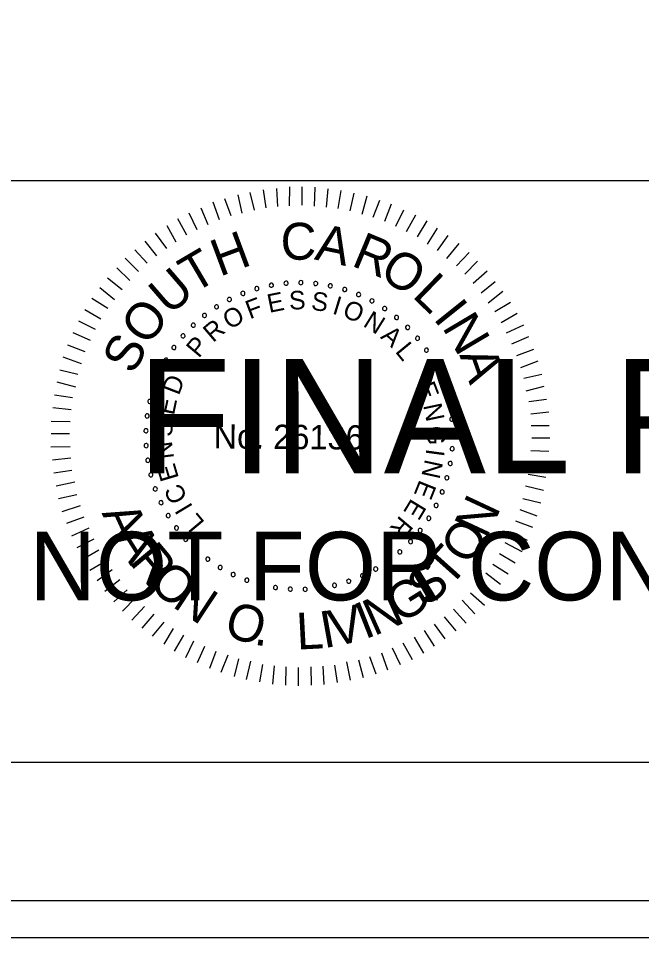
# Model space of a CAD drawing. Extents: x 967 to 1326, y 964 to 3144.
# Drawn here: x 1170.56 to 1189.3, y 1243.72 to 1271.36 of the extents above; entities that cross this region are included whole.
import ezdxf

# ---------------------------------------------------------------- set-up
doc = ezdxf.new("R2010")
doc.units = 0
for name, color, linetype in [('RD_XS_EwShp', 7, 'Continuous'), ('RD_XS_ExPaveRet', 7, 'Continuous'), ('RD_XS_TX_Elev_EX', 7, 'Continuous'), ('RD_XS_TX_Elev_PR', 7, 'Continuous'), ('RD_XS_TX_Station', 7, 'Continuous')]:
    doc.layers.add(name, color=color, linetype=linetype)

msp = doc.modelspace()

# ---------------------------------------------------------------- linework, layer by layer
at = {"layer": 'RD_XS_ExPaveRet'}
for points in [[(967.409, 1243.72), (1326.285, 1243.72), (1326.285, 1463.72), (967.409, 1463.72)], [(988.525, 1244.84), (1326.285, 1244.84), (1326.285, 1462.6), (988.525, 1462.6)]]:
    msp.add_lwpolyline(points, close=True, dxfattribs=at)
at = {"layer": 'RD_XS_TX_Elev_EX'}
for p, q in [((996.114, 1266.486), (1323.886, 1266.486)), ((1323.886, 1248.983), (996.114, 1248.983))]:
    msp.add_line(p, q, dxfattribs=at)
at = {"layer": 'RD_XS_TX_Elev_PR'}
for p, q in [((1178.01, 1265.663), (1177.93, 1266.209)), ((1178.364, 1265.699), (1178.33, 1266.244)), ((1178.717, 1265.719), (1178.722, 1266.295)), ((1179.093, 1265.739), (1179.098, 1266.292)), ((1179.469, 1265.713), (1179.489, 1266.288)), ((1179.829, 1265.687), (1179.872, 1266.231)), ((1180.174, 1265.646), (1180.271, 1266.19)), ((1176.964, 1265.419), (1176.769, 1265.935)), ((1177.287, 1265.508), (1177.169, 1266.054)), ((1177.657, 1265.597), (1177.53, 1266.128)), ((1180.535, 1265.573), (1180.662, 1266.102)), ((1180.902, 1265.478), (1181.045, 1266.022)), ((1176.264, 1265.156), (1176.053, 1265.657)), ((1176.61, 1265.306), (1176.423, 1265.83)), ((1181.231, 1265.384), (1181.428, 1265.896)), ((1181.584, 1265.265), (1181.78, 1265.786)), ((1175.933, 1265.005), (1175.699, 1265.506)), ((1181.905, 1265.109), (1182.154, 1265.606)), ((1182.226, 1264.953), (1182.506, 1265.45)), ((1175.308, 1264.634), (1175.036, 1265.12)), ((1175.624, 1264.846), (1175.352, 1265.332)), ((1182.562, 1264.789), (1182.85, 1265.27)), ((1175.03, 1264.445), (1174.681, 1264.9)), ((1182.86, 1264.572), (1183.163, 1265.053)), ((1183.158, 1264.378), (1183.484, 1264.828)), ((1174.729, 1264.217), (1174.372, 1264.665)), ((1183.447, 1264.145), (1183.811, 1264.587)), ((1174.435, 1263.997), (1174.062, 1264.399)), ((1183.729, 1263.92), (1184.116, 1264.316)), ((1174.172, 1263.753), (1173.776, 1264.148)), ((1183.98, 1263.672), (1184.368, 1264.061)), ((1173.909, 1263.479), (1173.52, 1263.858)), ((1184.232, 1263.394), (1184.657, 1263.767)), ((1173.684, 1263.197), (1173.242, 1263.546)), ((1184.475, 1263.108), (1184.892, 1263.45)), ((1173.451, 1262.9), (1173.009, 1263.256)), ((1184.687, 1262.807), (1185.128, 1263.156)), ((1173.257, 1262.64), (1172.776, 1262.936)), ((1173.039, 1262.312), (1172.559, 1262.6)), ((1184.885, 1262.544), (1185.355, 1262.832)), ((1185.081, 1262.213), (1185.56, 1262.493)), ((1172.883, 1262.006), (1172.379, 1262.256)), ((1185.24, 1261.904), (1185.756, 1262.145)), ((1172.727, 1261.677), (1172.215, 1261.904)), ((1185.399, 1261.573), (1185.907, 1261.791)), ((1172.571, 1261.333), (1172.051, 1261.53)), ((1185.549, 1261.226), (1186.057, 1261.414)), ((1172.461, 1260.974), (1171.91, 1261.178)), ((1185.669, 1260.865), (1186.185, 1261.06)), ((1172.351, 1260.652), (1171.807, 1260.787)), ((1185.759, 1260.541), (1186.297, 1260.667)), ((1172.286, 1260.276), (1171.727, 1260.419)), ((1185.832, 1260.165), (1186.371, 1260.298)), ((1172.191, 1259.955), (1171.647, 1260.029)), ((1185.906, 1259.842), (1186.436, 1259.906)), ((1172.15, 1259.587), (1171.598, 1259.653)), ((1185.964, 1259.473), (1186.51, 1259.53)), ((1172.124, 1259.234), (1171.548, 1259.239)), ((1185.977, 1259.12), (1186.514, 1259.115)), ((1172.105, 1258.866), (1171.545, 1258.871)), ((1185.997, 1258.751), (1186.542, 1258.747)), ((1172.118, 1258.482), (1171.542, 1258.471)), ((1185.971, 1258.368), (1186.508, 1258.348)), ((1172.138, 1258.136), (1171.585, 1258.072)), ((1185.952, 1258.022), (1186.497, 1257.949)), ((1172.173, 1257.768), (1171.627, 1257.688)), ((1185.888, 1257.655), (1186.417, 1257.566)), ((1172.262, 1257.414), (1171.701, 1257.296)), ((1185.808, 1257.302), (1186.345, 1257.175)), ((1172.321, 1257.037), (1171.774, 1256.911)), ((1185.729, 1256.926), (1186.265, 1256.792)), ((1172.425, 1256.707), (1171.871, 1256.519)), ((1185.634, 1256.597), (1186.146, 1256.401)), ((1172.53, 1256.36), (1172.007, 1256.173)), ((1185.508, 1256.253), (1186.013, 1256.057)), ((1172.681, 1256.029), (1172.165, 1255.788)), ((1172.831, 1255.705), (1172.323, 1255.441)), ((1185.352, 1255.924), (1185.857, 1255.675)), ((1185.188, 1255.603), (1185.7, 1255.33)), ((1172.982, 1255.374), (1172.497, 1255.094)), ((1185.024, 1255.274), (1185.498, 1254.987)), ((1173.194, 1255.042), (1172.709, 1254.762)), ((1184.822, 1254.946), (1185.288, 1254.658)), ((1173.384, 1254.78), (1172.936, 1254.453)), ((1184.62, 1254.687), (1185.055, 1254.353)), ((1173.612, 1254.478), (1173.164, 1254.129)), ((1184.403, 1254.389), (1184.814, 1254.033)), ((1173.832, 1254.177), (1173.437, 1253.812)), ((1184.155, 1254.092), (1184.574, 1253.72)), ((1174.091, 1253.945), (1173.689, 1253.541)), ((1183.899, 1253.864), (1184.28, 1253.454)), ((1174.35, 1253.674), (1173.97, 1253.263)), ((1183.644, 1253.597), (1184.024, 1253.18)), ((1174.64, 1253.442), (1174.275, 1253.022)), ((1174.937, 1253.209), (1174.58, 1252.782)), ((1183.358, 1253.37), (1183.715, 1252.944)), ((1175.212, 1253.014), (1174.932, 1252.549)), ((1182.764, 1252.952), (1183.059, 1252.482)), ((1183.065, 1253.141), (1183.384, 1252.709)), ((1175.525, 1252.812), (1175.245, 1252.331)), ((1182.463, 1252.755), (1182.743, 1252.269)), ((1175.83, 1252.633), (1175.588, 1252.136)), ((1176.159, 1252.477), (1175.94, 1251.98)), ((1181.8, 1252.431), (1182.041, 1251.93)), ((1182.124, 1252.581), (1182.396, 1252.08)), ((1176.503, 1252.321), (1176.307, 1251.816)), ((1176.855, 1252.211), (1176.651, 1251.69)), ((1177.177, 1252.1), (1177.05, 1251.572)), ((1181.122, 1252.175), (1181.31, 1251.652)), ((1181.476, 1252.28), (1181.664, 1251.771)), ((1177.545, 1252.036), (1177.409, 1251.484)), ((1177.897, 1251.933), (1177.808, 1251.412)), ((1178.25, 1251.892), (1178.207, 1251.34)), ((1178.603, 1251.866), (1178.598, 1251.313)), ((1178.978, 1251.84), (1178.974, 1251.295)), ((1179.355, 1251.86), (1179.365, 1251.307)), ((1179.715, 1251.88), (1179.749, 1251.327)), ((1180.061, 1251.915), (1180.149, 1251.393)), ((1180.423, 1252.012), (1180.541, 1251.458)), ((1180.791, 1252.07), (1180.926, 1251.54))]:
    msp.add_line(p, q, dxfattribs=at)
for centre, start, end in [((1178.609, 1263.397), 5.0653, 185.0653), ((1179.055, 1263.414), 359.5268, 179.5268), ((1179.055, 1263.414), 179.5268, 359.5268), ((1179.5, 1263.388), 353.9884, 173.9884), ((1177.312, 1263.091), 21.6807, 201.6807), ((1177.734, 1263.235), 16.1422, 196.1422), ((1177.734, 1263.235), 196.1422, 16.1422), ((1178.168, 1263.337), 10.6038, 190.6038), ((1178.168, 1263.337), 190.6038, 10.6038), ((1178.609, 1263.397), 185.0653, 5.0653), ((1179.5, 1263.388), 173.9884, 353.9884), ((1179.94, 1263.319), 168.4499, 348.4499), ((1179.94, 1263.319), 348.4499, 168.4499), ((1180.372, 1263.208), 162.9114, 342.9114), ((1180.372, 1263.208), 342.9114, 162.9114), ((1176.906, 1262.908), 27.2191, 207.2191), ((1176.906, 1262.908), 207.2191, 27.2191), ((1177.312, 1263.091), 201.6807, 21.6807), ((1180.79, 1263.056), 157.373, 337.373), ((1180.79, 1263.056), 337.373, 157.373), ((1181.193, 1262.864), 151.8345, 331.8345), ((1181.193, 1262.864), 331.8345, 151.8345), ((1176.52, 1262.686), 32.7576, 212.7576), ((1176.52, 1262.686), 212.7576, 32.7576), ((1181.574, 1262.634), 146.2961, 326.2961), ((1181.574, 1262.634), 326.2961, 146.2961), ((1176.156, 1262.428), 38.2961, 218.2961), ((1176.156, 1262.428), 218.2961, 38.2961), ((1181.932, 1262.368), 140.7576, 320.7576), ((1181.932, 1262.368), 320.7576, 140.7576), ((1175.82, 1262.135), 43.8345, 223.8345), ((1175.82, 1262.135), 223.8345, 43.8345), ((1182.263, 1262.069), 135.2191, 315.2191), ((1182.263, 1262.069), 315.2191, 135.2191), ((1175.513, 1261.812), 49.373, 229.373), ((1175.513, 1261.812), 229.373, 49.373), ((1182.563, 1261.74), 129.6807, 309.6807), ((1182.563, 1261.74), 309.6807, 129.6807), ((1175.239, 1261.461), 54.9114, 234.9114), ((1175.239, 1261.461), 234.9114, 54.9114), ((1182.83, 1261.383), 124.1422, 304.1422), ((1182.83, 1261.383), 304.1422, 124.1422), ((1175, 1261.085), 60.4499, 240.4499), ((1175, 1261.085), 240.4499, 60.4499), ((1183.061, 1261.002), 118.6038, 298.6038), ((1183.061, 1261.002), 298.6038, 118.6038), ((1174.798, 1260.687), 65.9884, 245.9884), ((1174.798, 1260.687), 245.9884, 65.9884), ((1183.255, 1260.601), 113.0653, 293.0653), ((1183.255, 1260.601), 293.0653, 113.0653), ((1174.636, 1260.272), 71.5268, 251.5268), ((1174.636, 1260.272), 251.5268, 71.5268), ((1183.408, 1260.182), 107.5268, 287.5268), ((1183.408, 1260.182), 287.5268, 107.5268), ((1174.514, 1259.843), 77.0653, 257.0653), ((1174.514, 1259.843), 257.0653, 77.0653), ((1183.521, 1259.751), 101.9884, 281.9884), ((1183.521, 1259.751), 281.9884, 101.9884), ((1174.435, 1259.405), 82.6038, 262.6038), ((1174.435, 1259.405), 262.6038, 82.6038), ((1183.592, 1259.311), 96.4499, 276.4499), ((1183.592, 1259.311), 276.4499, 96.4499), ((1174.398, 1258.961), 88.1422, 268.1422), ((1174.398, 1258.961), 268.1422, 88.1422), ((1183.619, 1258.866), 90.9114, 270.9114), ((1183.619, 1258.866), 270.9114, 90.9114), ((1174.404, 1258.515), 93.6807, 273.6807), ((1174.404, 1258.515), 273.6807, 93.6807), ((1183.604, 1258.421), 85.373, 265.373), ((1183.604, 1258.421), 265.373, 85.373), ((1174.453, 1258.072), 99.2191, 279.2191), ((1174.453, 1258.072), 279.2191, 99.2191), ((1183.546, 1257.979), 79.8345, 259.8345), ((1183.546, 1257.979), 259.8345, 79.8345), ((1174.545, 1257.636), 104.7576, 284.7576), ((1174.545, 1257.636), 284.7576, 104.7576), ((1183.445, 1257.545), 74.2961, 254.2961), ((1183.445, 1257.545), 254.2961, 74.2961), ((1174.678, 1257.211), 110.2961, 290.2961), ((1174.678, 1257.211), 290.2961, 110.2961), ((1183.303, 1257.122), 68.7576, 248.7576), ((1183.303, 1257.122), 248.7576, 68.7576), ((1174.852, 1256.8), 115.8345, 295.8345), ((1174.852, 1256.8), 295.8345, 115.8345), ((1183.121, 1256.716), 63.2191, 243.2191), ((1183.121, 1256.716), 243.2191, 63.2191), ((1175.065, 1256.409), 121.373, 301.373), ((1175.065, 1256.409), 301.373, 121.373), ((1182.9, 1256.328), 57.6807, 237.6807), ((1182.9, 1256.328), 237.6807, 57.6807), ((1175.314, 1256.039), 126.9114, 306.9114), ((1175.314, 1256.039), 306.9114, 126.9114), ((1182.643, 1255.964), 52.1422, 232.1422), ((1182.643, 1255.964), 232.1422, 52.1422), ((1175.598, 1255.696), 132.4499, 312.4499), ((1175.598, 1255.696), 312.4499, 132.4499), ((1182.353, 1255.627), 46.6038, 226.6038), ((1175.914, 1255.381), 137.9884, 317.9884), ((1175.914, 1255.381), 317.9884, 137.9884), ((1182.353, 1255.627), 226.6038, 46.6038), ((1176.258, 1255.099), 143.5268, 323.5268), ((1176.258, 1255.099), 323.5268, 143.5268), ((1182.03, 1255.319), 41.0653, 221.0653), ((1182.03, 1255.319), 221.0653, 41.0653), ((1176.629, 1254.851), 149.0653, 329.0653), ((1176.629, 1254.851), 329.0653, 149.0653), ((1181.305, 1254.803), 29.9884, 209.9884), ((1181.68, 1255.043), 35.5268, 215.5268), ((1181.68, 1255.043), 215.5268, 35.5268), ((1177.021, 1254.639), 154.6038, 334.6038), ((1177.021, 1254.639), 334.6038, 154.6038), ((1180.908, 1254.6), 24.4499, 204.4499), ((1180.908, 1254.6), 204.4499, 24.4499), ((1181.305, 1254.803), 209.9884, 29.9884), ((1177.432, 1254.467), 160.1422, 340.1422), ((1177.432, 1254.467), 340.1422, 160.1422), ((1177.858, 1254.335), 165.6807, 345.6807), ((1177.858, 1254.335), 345.6807, 165.6807), ((1178.294, 1254.245), 351.2191, 171.2191), ((1179.627, 1254.232), 7.8345, 187.8345), ((1180.065, 1254.313), 13.373, 193.373), ((1180.065, 1254.313), 193.373, 13.373), ((1180.494, 1254.436), 18.9114, 198.9114), ((1180.494, 1254.436), 198.9114, 18.9114), ((1178.294, 1254.245), 171.2191, 351.2191), ((1178.737, 1254.198), 356.7576, 176.7576), ((1178.737, 1254.198), 176.7576, 356.7576), ((1179.183, 1254.193), 2.2961, 182.2961), ((1179.183, 1254.193), 182.2961, 2.2961), ((1179.627, 1254.232), 187.8345, 7.8345)]:
    msp.add_arc(centre, 0.0627, start, end, dxfattribs=at)
at = {"layer": 'RD_XS_TX_Station'}
msp.add_lwpolyline([(967.409, 1243.72), (1326.285, 1243.72), (1326.285, 1463.72), (967.409, 1463.72)], close=True, dxfattribs=at)

# ---------------------------------------------------------------- texts
at = {"layer": 'RD_XS_EwShp'}
for s, height, p in [('FINAL PLANS', 3.4375, (1174.145, 1257.685)), ('NOT FOR CONSTRUCTION', 2.0625, (1170.901, 1253.86))]:
    msp.add_text(s, height=height, dxfattribs=at).set_placement(p)
at = {"layer": 'RD_XS_TX_Elev_PR'}
for s, height, rotation, p in [('C', 1.11, 359.5482, (1178.442, 1264.108)), ('A', 1.11, 348.1981, (1179.439, 1264.115)), ('H', 1.11, 20.3637, (1176.614, 1263.587)), ('R', 1.11, 337.4344, (1180.541, 1263.937)), ('T', 1.11, 30.4992, (1175.828, 1263.072)), ('O', 1.108, 326.5869, (1181.366, 1263.609)), ('U', 1.11, 40.8022, (1175.102, 1262.403)), ('L', 1.11, 315.9488, (1182.373, 1263.003)), ('E', 0.557, 11.4103, (1178.103, 1262.503)), ('S', 0.557, 2.208, (1178.709, 1262.601)), ('S', 0.557, 352.6608, (1179.346, 1262.599)), ('F', 0.557, 20.6127, (1177.52, 1262.309)), ('I', 0.557, 343.1136, (1179.975, 1262.491)), ('O', 0.557, 338.4392, (1180.274, 1262.401)), ('I', 1.11, 308.6613, (1183.011, 1262.338)), ('O', 1.11, 52.0267, (1174.435, 1261.474)), ('O', 0.557, 30.8477, (1176.917, 1261.987)), ('N', 0.557, 328.2042, (1180.896, 1262.12)), ('N', 1.11, 300.7037, (1183.285, 1262.075)), ('R', 0.557, 40.3949, (1176.415, 1261.594)), ('A', 0.557, 318.657, (1181.424, 1261.762)), ('S', 1.108, 63.2511, (1174.029, 1260.619)), ('P', 0.557, 49.9421, (1175.985, 1261.124)), ('L', 0.557, 309.4546, (1181.869, 1261.339)), ('A', 1.11, 289.4792, (1183.814, 1261.243)), ('D', 0.557, 69.0364, (1175.386, 1260.003)), ('E', 0.557, 291.049, (1182.53, 1260.307)), ('E', 0.557, 78.2388, (1175.238, 1259.407)), ('N', 0.557, 281.8466, (1182.728, 1259.726)), ('S', 0.557, 87.786, (1175.187, 1258.772)), ('No. 26136', 0.7311, 359.5268, (1176.429, 1258.43)), ('G', 0.557, 272.2995, (1182.833, 1259.097)), ('N', 0.557, 97.3332, (1175.242, 1258.137)), ('I', 0.557, 262.4084, (1182.83, 1258.437)), ('E', 0.557, 106.5355, (1175.394, 1257.541)), ('N', 0.557, 257.7339, (1182.789, 1258.127)), ('C', 0.557, 116.4266, (1175.661, 1256.938)), ('E', 0.557, 248.1867, (1182.628, 1257.511)), ('I', 0.557, 121.1011, (1175.823, 1256.67)), ('E', 0.557, 238.9844, (1182.378, 1256.949)), ('N', 1.105, 64.8922, (1184.632, 1255.684)), ('A', 1.105, 294.7297, (1173.062, 1256.486)), ('L', 0.557, 129.9595, (1176.187, 1256.204)), ('R', 0.557, 229.782, (1182.041, 1256.435)), ('A', 1.105, 302.2892, (1173.414, 1255.72)), ('O', 1.105, 56.2059, (1184.102, 1254.874)), ('R', 1.105, 309.8487, (1173.865, 1255.007)), ('T', 1.105, 48.2685, (1183.515, 1254.211)), ('O', 1.105, 317.7861, (1174.434, 1254.33)), ('S', 1.105, 40.3311, (1182.842, 1253.636)), ('N', 1.105, 326.4725, (1175.158, 1253.686)), ('G', 1.105, 32.0198, (1182.059, 1253.14)), ('N', 1.105, 24.0824, (1181.252, 1252.776)), ('O', 1.105, 342.3472, (1176.697, 1252.82)), ('V', 1.105, 12.7741, (1180.033, 1252.457)), ('I', 1.105, 21.4605, (1180.976, 1252.681)), ('L', 1.105, 2.9677, (1178.943, 1252.379)), ('I', 1.105, 10.1523, (1179.743, 1252.418)), ('.', 1.105, 351.0336, (1177.623, 1252.536))]:
    msp.add_text(s, height=height, rotation=rotation, dxfattribs=at).set_placement(p)

doc.saveas('drawing.dxf')
